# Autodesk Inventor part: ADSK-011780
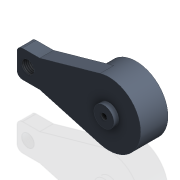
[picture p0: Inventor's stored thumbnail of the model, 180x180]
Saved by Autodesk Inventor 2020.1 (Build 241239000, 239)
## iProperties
Created: 1999-12
Part Number: ADSK-011780
Description: TENSIONER,ROTARY,RT1002
Document SubType Name: Modeling
Designer: cmcgourin
Material: Générique
Density: 1 g/cm^3
Appearance: Métal - Plomb
Mass: 154.628 g
Surface Area: 229.413 cm^2
Volume: 154.628 cm^3
Control State: 0
Checked Out: False
Master: False
Shininess: 0.0
Length Units: 11269
Angle Units: 11279
Time Units: 11290
Mass Units: 11283
Length Display Precision: 3
Angle Display Precision: 2
Compacted: True
Dimensions: 70x35,5x136 mm
Mass: 0,155 kg
VLT_Material: Generic
DocNumber: ADSK-011780.ipt
Folder: 01 - Themengebiete\Simplification\01 - Packaging machine\
VDS_Category: 3D Komponenten
Density: 0.0
Volumn: 0.0
Area: 0.0
PropertySet Name: Model Information
Author: cmcgourin
Revision Number: -
Title: bracket
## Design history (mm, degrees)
sketch "Sketch2"
  geometry: L1 (-95, -15)-(-76, -15); L2 (-76, -15)-(-9.468, -33.695); L3 (-101, -9)-(-101, 9); L4 (-95, 15)-(-76, 15); L5 (-76, 15)-(-9.468, 33.695); A1 r 35 centre (0, 0) between (-9.468, -33.695) and (-9.468, 33.695) reference; A2 r 6 centre (-95, -9) between (-101, -9) and (-95, -15); A3 r 6 centre (-95, 9) between (-95, 15) and (-101, 9); 4 further points
  constraints: 10 end point, 6 point on circle, 6 tangent, 4 point on line, 2 centre point, 2 horizontal alignment, 2 perpendicular, 1 equal radius, 1 horizontal, 1 midpoint
  dimensions: "d6" = 25 distance of point (-101, -15) L1.end; "d10" = 25 distance of point (-101, 15) L4.end; "d12" = 6 radius of A2; "d13" = 136 dimension on A1 L3; "d26" = 30 distance between parallel lines of L1 L4; "d28" = 12 distance from line of L3 point (-89, 0)
hole "Bohrung2" sketch "Sketch2" at (-89, 0) diameter "d31" = 13.835; stored, may be unused: countersink angle "d35" = 90 deg, drill point angle "d37" = 118 deg; dims "d32" = 32, "d33" = 17.3, "d34" = 2, "d36" = 41.3
node "Solide1"
  node "Extrusion1" dims "d1" = 15, "d2" = 0
  node "Extrusion3" dims "d17" = 5.5, "d18" = 0
  node "Hole1" dims "d19" = 6.647, "d20" = 9.525, "d21" = 6.35, "d22" = 60 deg, "d23" = 19.05, "d24" = 118 deg, "d27" = 16
sketch "Sketch1"
  geometry: C1 r 35 at (-29.067, -121.143)
  constraints: 1 centre point
  dimensions: "d0" = 70 diameter of C1
extrude "Extrusion4" join sketch "Sketch2" distance "d29" = 15; taper "d30" = 0 deg
sketch "Sketch3"
  geometry: C1 r 11 at (0, 0); A1 r 35 centre (0, 0) between (-9.468, -33.695) and (-9.468, 33.695) reference
  constraints: 1 centre point, 1 coincident
  dimensions: "d16" = 22 diameter of C1
sketch "Sketch4"
  geometry: C1 r 11 at (0, 0) reference; 1 further point
  constraints: 1 coincident
workplane "Work Plane1"
workplane "Work Plane3"
node "Corps solides"
node "Corps surfaciques"
other parameters: "d25" = -34.925
